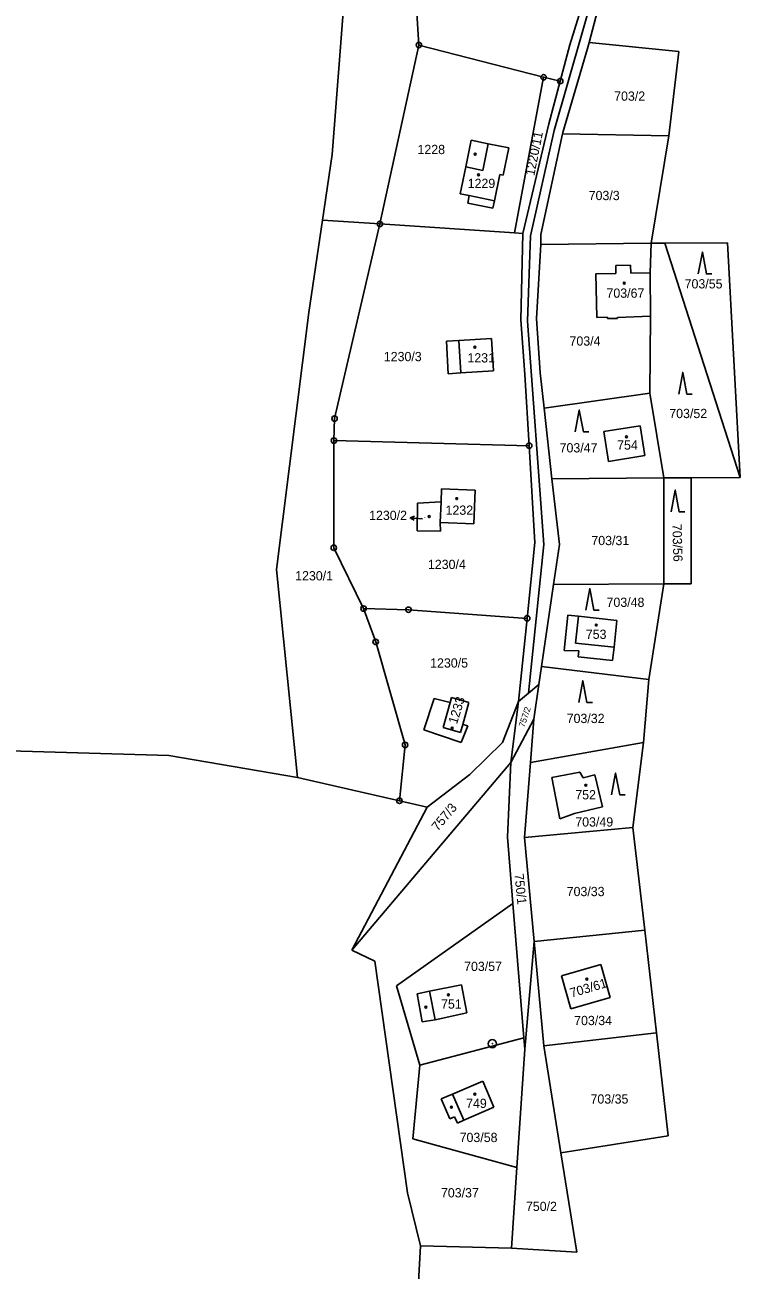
# Model space of a CAD drawing. Extents: x -779596 to -776743, y -1030330 to -1024513.
# Drawn here: x -779177.4 to -779046.1, y -1027552.3 to -1027323.5 of the extents above; entities that cross this region are included whole.
import ezdxf

# ---------------------------------------------------------------- set-up
doc = ezdxf.new("R2010")
doc.units = 0
for name, color, linetype in [('hranice parcel', 7, 'Continuous'), ('hranice vnitřní', 7, 'Continuous'), ('K_Ú_ hranice', 7, 'Continuous'), ('kultura', 7, 'Continuous'), ('Kód', 7, 'Continuous'), ('č_ parcel šipka', 7, 'Continuous'), ('č_pacel stav_', 7, 'Continuous'), ('č_parcel poz_', 7, 'Continuous')]:
    doc.layers.add(name, color=color, linetype=linetype)

msp = doc.modelspace()

# ---------------------------------------------------------------- linework, layer by layer
at = {"layer": 'hranice parcel'}
for points in [[(-779107.08, -1027295.35), (-779105.11, -1027327.16)], [(-779072.48, -1027315.68), (-779080.24, -1027342.85)], [(-779121, -1027347.3), (-779118.7, -1027317.15)], [(-779073.83, -1027326.68), (-779071.36, -1027317.3)], [(-779112.26, -1027360.04), (-779105.11, -1027327.16)], [(-779105.11, -1027327.16), (-779082.2, -1027333.09)], [(-779073.83, -1027326.68), (-779074.13, -1027327.82)], [(-779073.83, -1027326.68), (-779057.36, -1027328.34)], [(-779074.13, -1027327.82), (-779078.69, -1027343.2)], [(-779059.19, -1027343.84), (-779057.36, -1027328.34)], [(-779087.56, -1027361.64), (-779082.2, -1027333.09)], [(-779082.2, -1027333.09), (-779079.14, -1027333.78)], [(-779080.24, -1027342.85), (-779084.58, -1027362.21)], [(-779078.75, -1027343.5), (-779082.68, -1027361.99)], [(-779078.69, -1027343.2), (-779078.75, -1027343.5)], [(-779078.75, -1027343.5), (-779059.19, -1027343.84)], [(-779096.5, -1027349.54), (-779095.52, -1027344.66)], [(-779095.52, -1027344.66), (-779092.35, -1027345.3)], [(-779092.35, -1027345.3), (-779088.61, -1027346.05)], [(-779089.62, -1027351.07), (-779088.61, -1027346.05)], [(-779062.42, -1027363.6), (-779059.19, -1027343.84)], [(-779122.78, -1027359.36), (-779121, -1027347.3)], [(-779097.5, -1027354.5), (-779096.5, -1027349.54)], [(-779091.23, -1027355.76), (-779090.26, -1027350.94)], [(-779090.26, -1027350.94), (-779089.62, -1027351.07)], [(-779097.5, -1027354.5), (-779095.87, -1027354.83)], [(-779096.14, -1027356.2), (-779095.87, -1027354.83)], [(-779096.14, -1027356.2), (-779091.5, -1027357.12)], [(-779091.5, -1027357.12), (-779091.23, -1027355.76)], [(-779125.29, -1027376.3), (-779122.78, -1027359.36)], [(-779122.78, -1027359.36), (-779112.26, -1027360.04)], [(-779120.59, -1027395.81), (-779112.26, -1027360.04)], [(-779112.26, -1027360.04), (-779087.56, -1027361.64)], [(-779087.56, -1027361.64), (-779086.02, -1027361.78)], [(-779082.72, -1027363.8), (-779082.68, -1027361.99)], [(-779084.58, -1027362.21), (-779085.16, -1027377.89)], [(-779082.72, -1027363.8), (-779083.51, -1027377.41)], [(-779082.72, -1027363.8), (-779062.42, -1027363.6)], [(-779062.42, -1027363.6), (-779062.66, -1027369.05)], [(-779062.42, -1027363.6), (-779059.92, -1027363.58)], [(-779059.92, -1027363.58), (-779048.42, -1027363.49)], [(-779046.12, -1027406.62), (-779059.92, -1027363.58)], [(-779048.42, -1027363.49), (-779046.12, -1027406.62)], [(-779068.95, -1027367.66), (-779066.22, -1027367.62)], [(-779068.93, -1027369.16), (-779068.95, -1027367.66)], [(-779066.22, -1027367.62), (-779066.2, -1027369.1)], [(-779072.61, -1027369.2), (-779068.93, -1027369.16)], [(-779072.42, -1027377.26), (-779072.61, -1027369.2)], [(-779066.2, -1027369.1), (-779062.66, -1027369.05)], [(-779062.66, -1027369.05), (-779062.55, -1027377)], [(-779131.23, -1027423.55), (-779125.29, -1027376.3)], [(-779085.16, -1027377.89), (-779082.15, -1027418.95)], [(-779083.51, -1027377.41), (-779082.85, -1027387.39)], [(-779070.46, -1027377.18), (-779072.42, -1027377.26)], [(-779070.45, -1027377.42), (-779070.46, -1027377.18)], [(-779068.67, -1027377.42), (-779070.45, -1027377.42)], [(-779068.66, -1027377.25), (-779068.67, -1027377.42)], [(-779062.55, -1027377), (-779068.66, -1027377.25)], [(-779062.55, -1027377), (-779062.67, -1027391.13)], [(-779100.05, -1027381.59), (-779097.79, -1027381.46)], [(-779100.05, -1027381.59), (-779099.73, -1027387.56)], [(-779097.79, -1027381.46), (-779091.77, -1027381.09)], [(-779091.77, -1027381.09), (-779091.41, -1027387.05)], [(-779097.43, -1027387.42), (-779091.41, -1027387.05)], [(-779099.73, -1027387.56), (-779097.43, -1027387.42)], [(-779082.12, -1027393.89), (-779082.85, -1027387.39)], [(-779062.67, -1027391.13), (-779082.12, -1027393.89)], [(-779062.67, -1027391.13), (-779060.13, -1027406.72)], [(-779080.67, -1027406.86), (-779082.12, -1027393.89)], [(-779120.71, -1027399.85), (-779120.59, -1027395.81)], [(-779071.17, -1027398.21), (-779064.48, -1027397.12)], [(-779070.27, -1027403.67), (-779071.17, -1027398.21)], [(-779064.48, -1027397.12), (-779063.59, -1027402.58)], [(-779120.73, -1027419.56), (-779120.71, -1027399.85)], [(-779120.71, -1027399.85), (-779084.85, -1027400.79)], [(-779063.59, -1027402.58), (-779070.27, -1027403.67)], [(-779060.13, -1027406.72), (-779080.67, -1027406.86)], [(-779080.67, -1027406.86), (-779079.31, -1027418.98)], [(-779060.13, -1027406.72), (-779055.13, -1027406.69)], [(-779060.1, -1027426.19), (-779060.13, -1027406.72)], [(-779055.13, -1027406.69), (-779046.12, -1027406.62)], [(-779055.13, -1027406.69), (-779055.11, -1027426.16)], [(-779101.04, -1027411.13), (-779100.95, -1027408.73)], [(-779100.95, -1027408.73), (-779094.76, -1027408.98)], [(-779095, -1027415.17), (-779094.76, -1027408.98)], [(-779105.41, -1027416.44), (-779105.34, -1027411.34)], [(-779105.34, -1027411.34), (-779101.04, -1027411.13)], [(-779101.19, -1027414.93), (-779101.04, -1027411.13)], [(-779105.41, -1027416.44), (-779101.11, -1027416.53)], [(-779101.19, -1027414.93), (-779101.11, -1027416.53)], [(-779101.19, -1027414.93), (-779095, -1027415.17)], [(-779082.15, -1027418.95), (-779084.98, -1027446.3)], [(-779080.37, -1027426.31), (-779079.31, -1027418.98)], [(-779120.73, -1027419.56), (-779115.26, -1027430.72)], [(-779131.23, -1027423.55), (-779127.38, -1027461.75)], [(-779060.1, -1027426.19), (-779080.37, -1027426.31)], [(-779060.1, -1027426.19), (-779062.86, -1027443.77)], [(-779055.11, -1027426.16), (-779060.1, -1027426.19)], [(-779080.37, -1027426.31), (-779082.56, -1027441.36)], [(-779115.26, -1027430.72), (-779113.03, -1027436.85)], [(-779115.26, -1027430.72), (-779107.01, -1027430.94)], [(-779107.01, -1027430.94), (-779085.22, -1027432.53)], [(-779078.42, -1027438.45), (-779077.72, -1027431.93)], [(-779077.72, -1027431.93), (-779075.81, -1027432.13)], [(-779075.81, -1027432.13), (-779068.73, -1027432.89)], [(-779068.73, -1027432.89), (-779069.27, -1027437.82)], [(-779113.03, -1027436.85), (-779107.63, -1027455.78)], [(-779075.76, -1027438.52), (-779078.42, -1027438.45)], [(-779075.87, -1027439.59), (-779075.76, -1027438.52)], [(-779069.54, -1027440.29), (-779075.87, -1027439.59)], [(-779069.27, -1027437.82), (-779069.54, -1027440.29)], [(-779083.05, -1027444.7), (-779082.56, -1027441.36)], [(-779062.86, -1027443.77), (-779082.56, -1027441.36)], [(-779062.86, -1027443.77), (-779063.85, -1027455.32)], [(-779086.8, -1027447.82), (-779084.98, -1027446.3)], [(-779084.98, -1027446.3), (-779083.05, -1027444.7)], [(-779083.97, -1027451.07), (-779083.05, -1027444.7)], [(-779104.22, -1027453.01), (-779102.28, -1027447.27)], [(-779102.28, -1027447.27), (-779099.36, -1027448.02)], [(-779099.36, -1027448.02), (-779099.11, -1027447.1)], [(-779099.11, -1027447.1), (-779095.92, -1027447.99)], [(-779097.04, -1027452.04), (-779095.92, -1027447.99)], [(-779086.8, -1027447.82), (-779088.24, -1027459.01)], [(-779083.97, -1027451.07), (-779088.24, -1027459.01)], [(-779084.61, -1027459.04), (-779083.97, -1027451.07)], [(-779104.22, -1027453.01), (-779097.32, -1027455.32)], [(-779097.32, -1027455.32), (-779096.13, -1027452.29)], [(-779097.04, -1027452.04), (-779096.13, -1027452.29)], [(-779108.67, -1027466.06), (-779107.63, -1027455.78)], [(-779063.85, -1027455.32), (-779084.61, -1027459.04)], [(-779063.85, -1027455.32), (-779065.8, -1027470.94)], [(-779186.59, -1027456.72), (-779151.03, -1027457.76)], [(-779151.03, -1027457.76), (-779127.38, -1027461.75)], [(-779088.24, -1027459.01), (-779117.41, -1027493.49)], [(-779088.24, -1027459.01), (-779088.85, -1027472.76)], [(-779085.71, -1027472.8), (-779084.61, -1027459.04)], [(-779127.38, -1027461.75), (-779108.67, -1027466.06)], [(-779080.68, -1027461.76), (-779075.55, -1027460.77)], [(-779079.22, -1027469.38), (-779080.68, -1027461.76)], [(-779075.55, -1027460.77), (-779074.91, -1027461.81)], [(-779074.91, -1027461.81), (-779072.77, -1027461.31)], [(-779072.77, -1027461.31), (-779071.38, -1027467.16)], [(-779108.67, -1027466.06), (-779103.61, -1027467.22)], [(-779071.38, -1027467.16), (-779076.5, -1027468.37)], [(-779076.5, -1027468.37), (-779079.22, -1027469.38)], [(-779065.8, -1027470.94), (-779085.71, -1027472.8)], [(-779065.8, -1027470.94), (-779063.64, -1027489.82)], [(-779088.85, -1027472.76), (-779087.86, -1027484.91)], [(-779083.93, -1027491.92), (-779085.71, -1027472.8)], [(-779087.86, -1027484.91), (-779109.23, -1027500.06)], [(-779087.86, -1027484.91), (-779085.83, -1027509.63)], [(-779063.64, -1027489.82), (-779083.93, -1027491.92)], [(-779063.64, -1027489.82), (-779061.47, -1027508.69)], [(-779085.66, -1027511.72), (-779083.93, -1027491.92)], [(-779082.14, -1027511.07), (-779083.93, -1027491.92)], [(-779078.92, -1027498.24), (-779071.67, -1027496.17)], [(-779071.67, -1027496.17), (-779069.95, -1027502.21)], [(-779077.21, -1027504.32), (-779078.92, -1027498.24)], [(-779109.23, -1027500.06), (-779104.92, -1027514.63)], [(-779105.41, -1027501.52), (-779103.13, -1027501.07)], [(-779104.53, -1027506.69), (-779105.41, -1027501.52)], [(-779103.13, -1027501.07), (-779097.3, -1027499.91)], [(-779097.3, -1027499.91), (-779096.28, -1027505.05)], [(-779069.95, -1027502.21), (-779077.21, -1027504.32)], [(-779102.09, -1027506.29), (-779104.53, -1027506.69)], [(-779096.28, -1027505.05), (-779102.09, -1027506.29)], [(-779104.92, -1027514.63), (-779085.83, -1027509.63)], [(-779085.83, -1027509.63), (-779085.66, -1027511.72)], [(-779061.47, -1027508.69), (-779082.14, -1027511.07)], [(-779061.47, -1027508.69), (-779059.3, -1027527.63)], [(-779087.12, -1027533.47), (-779085.66, -1027511.72)], [(-779079.01, -1027530.75), (-779082.14, -1027511.07)], [(-779106.22, -1027528.18), (-779104.92, -1027514.63)], [(-779098.93, -1027519.96), (-779093.39, -1027517.58)], [(-779093.39, -1027517.58), (-779091.32, -1027522.39)], [(-779100.99, -1027520.85), (-779098.93, -1027519.96)], [(-779099.41, -1027524.51), (-779100.99, -1027520.85)], [(-779098.54, -1027524.14), (-779099.41, -1027524.51)], [(-779098.03, -1027525.33), (-779098.54, -1027524.14)], [(-779091.32, -1027522.39), (-779096.86, -1027524.78)], [(-779096.86, -1027524.78), (-779098.03, -1027525.33)], [(-779100.43, -1027529.78), (-779106.22, -1027528.18)], [(-779059.3, -1027527.63), (-779079.01, -1027530.75)], [(-779087.12, -1027533.47), (-779100.43, -1027529.78)], [(-779076.12, -1027548.99), (-779079.01, -1027530.75)], [(-779087.12, -1027533.47), (-779088.12, -1027548.31)], [(-779104.83, -1027547.87), (-779088.12, -1027548.31)], [(-779088.12, -1027548.31), (-779076.12, -1027548.99)]]:
    msp.add_lwpolyline(points, dxfattribs=at)
at = {"layer": 'hranice vnitřní'}
for points in [[(-779093.33, -1027350.2), (-779092.35, -1027345.3)], [(-779096.5, -1027349.54), (-779093.33, -1027350.2)], [(-779095.87, -1027354.83), (-779091.23, -1027355.76)], [(-779097.79, -1027381.46), (-779097.43, -1027387.42)], [(-779075.81, -1027432.13), (-779076.34, -1027437.06)], [(-779076.34, -1027437.06), (-779069.27, -1027437.82)], [(-779100.64, -1027452.59), (-779099.36, -1027448.02)], [(-779100.64, -1027452.59), (-779097.45, -1027453.48)], [(-779097.45, -1027453.48), (-779097.04, -1027452.04)], [(-779102.09, -1027506.29), (-779103.13, -1027501.07)], [(-779098.93, -1027519.96), (-779096.86, -1027524.78)]]:
    msp.add_lwpolyline(points, dxfattribs=at)
at = {"layer": 'K_Ú_ hranice'}
for points in [[(-779077.39, -1027327.14), (-779071.16, -1027306.98)], [(-779079.14, -1027333.78), (-779077.39, -1027327.14)], [(-779081.21, -1027341.65), (-779079.14, -1027333.78)], [(-779086.02, -1027361.78), (-779081.21, -1027341.65)], [(-779086.4, -1027377.64), (-779086.02, -1027361.78)], [(-779086.4, -1027377.64), (-779085.64, -1027387.71)], [(-779085.64, -1027387.71), (-779084.85, -1027400.79)], [(-779084.85, -1027400.79), (-779083.78, -1027418.61)], [(-779085.22, -1027432.53), (-779083.78, -1027418.61)], [(-779086.8, -1027447.82), (-779085.22, -1027432.53)], [(-779089.76, -1027455.33), (-779086.8, -1027447.82)], [(-779095.74, -1027461.21), (-779089.76, -1027455.33)], [(-779103.61, -1027467.22), (-779095.74, -1027461.21)], [(-779117.41, -1027493.49), (-779103.61, -1027467.22)], [(-779117.41, -1027493.49), (-779113.17, -1027495.55)], [(-779113.17, -1027495.55), (-779107.17, -1027538.1)], [(-779107.17, -1027538.1), (-779104.83, -1027547.87)], [(-779105.23, -1027555.63), (-779104.83, -1027547.87)]]:
    msp.add_lwpolyline(points, dxfattribs=at)
at = {"layer": 'kultura'}
for points in [[(-779053.79, -1027369.21), (-779053.04, -1027365.21), (-779052.29, -1027369.21), (-779051.29, -1027369.21)], [(-779057.39, -1027391.32), (-779056.64, -1027387.32), (-779055.89, -1027391.32), (-779054.89, -1027391.32)], [(-779076.4, -1027398.24), (-779075.65, -1027394.24), (-779074.9, -1027398.24), (-779073.9, -1027398.24)], [(-779058.78, -1027412.95), (-779058.03, -1027408.95), (-779057.28, -1027412.95), (-779056.28, -1027412.95)], [(-779074.47, -1027431.05), (-779073.72, -1027427.05), (-779072.97, -1027431.05), (-779071.97, -1027431.05)], [(-779075.75, -1027447.98), (-779075, -1027443.98), (-779074.25, -1027447.98), (-779073.25, -1027447.98)], [(-779069.72, -1027464.95), (-779068.97, -1027460.95), (-779068.22, -1027464.95), (-779067.22, -1027464.95)]]:
    msp.add_lwpolyline(points, dxfattribs=at)
for centre in [(-779094.75, -1027347.22), (-779094.15, -1027351), (-779067.38, -1027370.92), (-779094.81, -1027382.69), (-779066.98, -1027399.17), (-779098.16, -1027410.52), (-779103.21, -1027413.82), (-779072.52, -1027433.75), (-779099, -1027452.71), (-779074.46, -1027463.21), (-779074.25, -1027498.82), (-779099.69, -1027501.73), (-779103.81, -1027503.98), (-779094.83, -1027519.99), (-779099.14, -1027522.36)]:
    msp.add_circle(centre, 0.175, dxfattribs=at)
at = {"layer": 'Kód'}
for centre, radius in [((-779105.11, -1027327.16), 0.5), ((-779105.11, -1027327.16), 0.032), ((-779082.2, -1027333.09), 0.5), ((-779082.2, -1027333.09), 0.032), ((-779079.14, -1027333.78), 0.5), ((-779079.14, -1027333.78), 0.032), ((-779112.26, -1027360.04), 0.5), ((-779112.26, -1027360.04), 0.032), ((-779120.59, -1027395.81), 0.5), ((-779120.59, -1027395.81), 0.032), ((-779120.71, -1027399.85), 0.5), ((-779120.71, -1027399.85), 0.032), ((-779084.85, -1027400.79), 0.5), ((-779084.85, -1027400.79), 0.032), ((-779120.73, -1027419.56), 0.5), ((-779120.73, -1027419.56), 0.032), ((-779115.26, -1027430.72), 0.5), ((-779115.26, -1027430.72), 0.032), ((-779107.01, -1027430.94), 0.5), ((-779107.01, -1027430.94), 0.032), ((-779085.22, -1027432.53), 0.5), ((-779085.22, -1027432.53), 0.032), ((-779113.03, -1027436.85), 0.5), ((-779113.03, -1027436.85), 0.032), ((-779107.63, -1027455.78), 0.5), ((-779107.63, -1027455.78), 0.032), ((-779108.67, -1027466.06), 0.5), ((-779108.67, -1027466.06), 0.032), ((-779091.62, -1027510.7), 0.75), ((-779091.62, -1027510.7), 0.032)]:
    msp.add_circle(centre, radius, dxfattribs=at)
at = {"layer": 'č_ parcel šipka'}
for points in [[(-779105.981, -1027414.491), (-779106.704, -1027414.067), (-779105.93, -1027413.744)], [(-779104.46, -1027414.22), (-779106.704, -1027414.067)]]:
    msp.add_lwpolyline(points, dxfattribs=at)

# ---------------------------------------------------------------- texts
msp.add_text('1230/2', height=1.7, dxfattribs=at).set_placement((-779114.24, -1027414.45))
at = {"layer": 'č_pacel stav_'}
for s, height, p in [('1229', 1.7, (-779096.14, -1027353.43)), ('703/67', 1.7, (-779070.65, -1027373.6)), ('1231', 1.7, (-779096.19, -1027385.5)), ('1232', 1.7, (-779100.2, -1027413.49)), ('1230/2', 0.1, (-779104.26, -1027414.02)), ('753', 1.7, (-779074.45, -1027436.3)), ('752', 1.7, (-779076.38, -1027465.8)), ('751', 1.7, (-779101.03, -1027504.25)), ('749', 1.7, (-779096.43, -1027522.51))]:
    msp.add_text(s, height=height, dxfattribs=at).set_placement(p)
for s, rotation, p in [('1233', 72.90058, (-779098.112, -1027452.071)), ('703/61', 16.50013, (-779077.084, -1027502.246))]:
    msp.add_text(s, height=1.7, rotation=rotation, dxfattribs=at).set_placement(p)
at = {"layer": 'č_parcel poz_'}
for s, p in [('703/2', (-779069.24, -1027337.39)), ('1228', (-779105.36, -1027347.2)), ('703/3', (-779073.92, -1027355.66)), ('703/55', (-779056.3, -1027371.89)), ('703/4', (-779077.44, -1027382.4)), ('1230/3', (-779111.54, -1027385.26)), ('703/52', (-779059.12, -1027395.72)), ('703/47', (-779079.26, -1027402.03)), ('754', (-779068.7, -1027401.52)), ('703/31', (-779073.43, -1027419.07)), ('1230/1', (-779127.82, -1027425.55)), ('1230/4', (-779103.44, -1027423.46)), ('703/48', (-779070.64, -1027430.42)), ('1230/5', (-779103.03, -1027441.57)), ('703/32', (-779077.96, -1027451.77)), ('703/49', (-779076.38, -1027470.79)), ('703/33', (-779077.96, -1027483.58)), ('703/57', (-779096.8, -1027497.34)), ('703/34', (-779076.59, -1027507.29)), ('703/35', (-779073.58, -1027521.71)), ('703/58', (-779097.62, -1027528.78)), ('703/37', (-779101.05, -1027538.95)), ('750/2', (-779085.443, -1027541.45))]:
    msp.add_text(s, height=1.7, dxfattribs=at).set_placement(p)
for s, height, rotation, p in [('1220/11', 1.7, 78.70063, (-779083.916, -1027351.275)), ('703/56', 1.7, 271.70216, (-779058.565, -1027415.193)), ('757/2', 1.14, 71.70057, (-779085.723, -1027452.63)), ('757/3', 1.7, 50.2004, (-779101.629, -1027471.744)), ('750/1', 1.7, 275.90219, (-779087.571, -1027479.522))]:
    msp.add_text(s, height=height, rotation=rotation, dxfattribs=at).set_placement(p)

doc.saveas('drawing.dxf')
